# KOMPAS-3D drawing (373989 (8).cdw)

Referenced files: Спецификация для сборочного.cdw
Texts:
  ТМАШ.ПДТО.00.000
  Приспособление для  токарной операции
  Серега
  Текст на чертеже
  Размерные надписи
  Шероховатость
  Линия-выноска #1
  Линия-выноска #2
  Линия-выноска #3
  Отклонения формы и база
  Заголовок таблицы
  Ячейка таблицы
  Стрелка вида
  Обозначение изменения
  Фигурная скобка
  Номер узла
  Марка координационной оси
  VRCB
  Выносная надпись
  Обозначение узла
  Марка/позиционное обозначение с линией-выноской
  Марка/позиционное обозначение на линии
  Марка/позиционное обозначение без линии-выноски
  Олейник
  ЧГАА кафедра
  ТМАШ, гр Т-51
  ТМАШ.ПДФО.00.000  -
  Документация
  Сборочный чертеж
  Детали
  ТМАШ.ПДТО.00.000 СБ
  ГОСТ 8918-69
  Шайба 7019-0502
  ГОСТ 4087-69
  Шпилька М 20 70 20 46
  Приспособление для
  токарной операции
  ТМАШ.ПДТО.00.001
  ТМАШ.ПДТО.00.002
  Оправка
  Кольцо промежуточное
  Штифт 6Г 45
  ГОСТ 3128-70
  Стандартные изделия
  Гайка 7003-0306
Dimensions and other numbers on the sheet: 7; 1:1; 1; 2; 9; 6; 8; 0; 3; 4; 5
